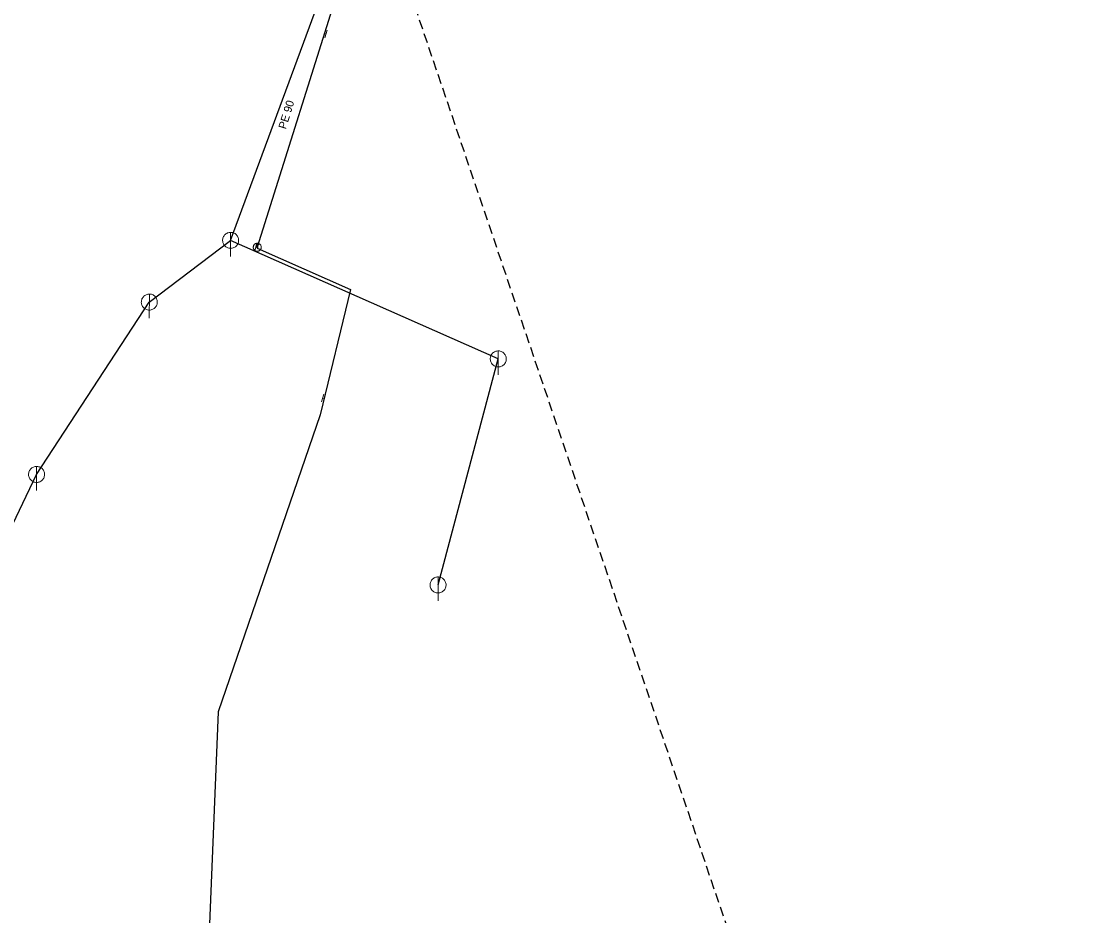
# Model space of a CAD drawing. Extents: x -659250 to -657316, y -997555 to -993684.
# Drawn here: x -658490.2 to -658358.7, y -994287.5 to -994175.8 of the extents above; entities that cross this region are included whole.
import ezdxf

# ---------------------------------------------------------------- set-up
doc = ezdxf.new("R2010")
doc.units = 0
doc.header["$LTSCALE"] = 0.4
doc.linetypes.add('MEDIUM_DASHED', pattern=[4.5, 3, -1.5])
doc.layers.add('1', color=7, linetype='Continuous')
for name, color, linetype, lineweight in [('14', 7, 'Continuous', 25), ('17', 7, 'Continuous', 25), ('22', 7, 'Continuous', 13), ('34', 7, 'Continuous', 13), ('47', 7, 'Continuous', 13), ('63', 7, 'MEDIUM_DASHED', 25), ('9', 7, 'Continuous', 13)]:
    doc.layers.add(name, color=color, linetype=linetype, lineweight=lineweight)

msp = doc.modelspace()

# ---------------------------------------------------------------- linework, layer by layer
at = {"layer": '14', "lineweight": 13}
for p, q in [((-658452.347, -994177.312), (-658452.14, -994177.379)), ((-658452.359, -994222.893), (-658452.55, -994222.84))]:
    msp.add_line(p, q, dxfattribs=at)
at = {"layer": '14'}
for p, q in [((-658430.62, -994217.949), (-658464.05, -994203.14)), ((-658488.28, -994232.379), (-658474.199, -994210.85)), ((-658438.14, -994246.18), (-658430.62, -994217.949))]:
    msp.add_line(p, q, dxfattribs=at)
for points in [[(-658474.199, -994210.85), (-658464.05, -994203.14), (-658452.78, -994172.6)], [(-658503.5, -994286.66), (-658500.649, -994258.26), (-658488.28, -994232.379)]]:
    msp.add_lwpolyline(points, dxfattribs=at)
at = {"layer": '14', "lineweight": 13}
msp.add_lwpolyline([(-658460.72, -994204.005), (-658460.899, -994203.96), (-658460.68, -994203.62)], dxfattribs=at)
at = {"layer": '17'}
for points in [[(-658452.813, -994094.017), (-658447.552, -994118.497), (-658457.625, -994125.125), (-658454.477, -994135.613), (-658450.198, -994170.463), (-658460.72, -994204.005)], [(-658460.72, -994204.005), (-658460.75, -994204.1), (-658449.09, -994209.27), (-658452.845, -994224.92), (-658465.59, -994262.02), (-658467.846, -994317.061), (-658460.533, -994343.112)]]:
    msp.add_lwpolyline(points, dxfattribs=at)
at = {"layer": '22'}
for p, q in [((-658464.05, -994205.14), (-658464.049, -994202.14)), ((-658474.199, -994212.85), (-658474.198, -994209.85)), ((-658430.62, -994219.949), (-658430.619, -994216.949)), ((-658488.28, -994234.379), (-658488.279, -994231.379)), ((-658438.14, -994248.18), (-658438.139, -994245.18))]:
    msp.add_line(p, q, dxfattribs=at)
for points in [[(-658463.05, -994203.14), (-658463.055, -994203.031), (-658463.073, -994202.923), (-658463.103, -994202.817), (-658463.143, -994202.716), (-658463.195, -994202.619), (-658463.257, -994202.529), (-658463.329, -994202.446), (-658463.409, -994202.372), (-658463.497, -994202.306), (-658463.591, -994202.251), (-658463.691, -994202.206), (-658463.796, -994202.173), (-658463.903, -994202.151), (-658464.012, -994202.141), (-658464.122, -994202.143), (-658464.23, -994202.157), (-658464.337, -994202.182), (-658464.44, -994202.219), (-658464.538, -994202.268), (-658464.63, -994202.326), (-658464.716, -994202.395), (-658464.793, -994202.472), (-658464.862, -994202.558), (-658464.921, -994202.65), (-658464.969, -994202.748), (-658465.006, -994202.851), (-658465.032, -994202.958), (-658465.046, -994203.066), (-658465.049, -994203.176), (-658465.039, -994203.285), (-658465.018, -994203.392), (-658464.984, -994203.496), (-658464.94, -994203.596), (-658464.885, -994203.691), (-658464.819, -994203.779), (-658464.745, -994203.859), (-658464.662, -994203.931), (-658464.572, -994203.993), (-658464.476, -994204.045), (-658464.374, -994204.086), (-658464.269, -994204.116), (-658464.161, -994204.134), (-658464.051, -994204.14), (-658463.942, -994204.134), (-658463.834, -994204.116), (-658463.729, -994204.087), (-658463.627, -994204.046), (-658463.53, -994203.994), (-658463.44, -994203.932), (-658463.357, -994203.861), (-658463.282, -994203.781), (-658463.217, -994203.693), (-658463.161, -994203.599), (-658463.117, -994203.499), (-658463.083, -994203.395), (-658463.061, -994203.287), (-658463.051, -994203.178)], [(-658473.199, -994210.85), (-658473.204, -994210.741), (-658473.222, -994210.633), (-658473.252, -994210.527), (-658473.292, -994210.426), (-658473.344, -994210.329), (-658473.406, -994210.239), (-658473.478, -994210.156), (-658473.558, -994210.082), (-658473.646, -994210.016), (-658473.74, -994209.961), (-658473.84, -994209.916), (-658473.945, -994209.883), (-658474.052, -994209.861), (-658474.161, -994209.851), (-658474.271, -994209.853), (-658474.379, -994209.867), (-658474.486, -994209.892), (-658474.589, -994209.929), (-658474.687, -994209.978), (-658474.779, -994210.036), (-658474.865, -994210.105), (-658474.942, -994210.182), (-658475.011, -994210.268), (-658475.07, -994210.36), (-658475.118, -994210.458), (-658475.155, -994210.561), (-658475.181, -994210.668), (-658475.195, -994210.776), (-658475.198, -994210.886), (-658475.188, -994210.995), (-658475.167, -994211.102), (-658475.133, -994211.206), (-658475.089, -994211.306), (-658475.034, -994211.401), (-658474.968, -994211.489), (-658474.894, -994211.569), (-658474.811, -994211.641), (-658474.721, -994211.703), (-658474.625, -994211.755), (-658474.523, -994211.796), (-658474.418, -994211.826), (-658474.31, -994211.844), (-658474.2, -994211.85), (-658474.091, -994211.844), (-658473.983, -994211.826), (-658473.878, -994211.797), (-658473.776, -994211.756), (-658473.679, -994211.704), (-658473.589, -994211.642), (-658473.506, -994211.571), (-658473.431, -994211.491), (-658473.366, -994211.403), (-658473.31, -994211.309), (-658473.266, -994211.209), (-658473.232, -994211.105), (-658473.21, -994210.997), (-658473.2, -994210.888)], [(-658429.62, -994217.949), (-658429.625, -994217.84), (-658429.643, -994217.732), (-658429.673, -994217.626), (-658429.713, -994217.525), (-658429.765, -994217.428), (-658429.827, -994217.338), (-658429.899, -994217.255), (-658429.979, -994217.181), (-658430.067, -994217.115), (-658430.161, -994217.06), (-658430.261, -994217.015), (-658430.366, -994216.982), (-658430.473, -994216.96), (-658430.582, -994216.95), (-658430.692, -994216.952), (-658430.8, -994216.966), (-658430.907, -994216.991), (-658431.01, -994217.028), (-658431.108, -994217.077), (-658431.2, -994217.135), (-658431.286, -994217.204), (-658431.363, -994217.281), (-658431.432, -994217.367), (-658431.491, -994217.459), (-658431.539, -994217.557), (-658431.576, -994217.66), (-658431.602, -994217.767), (-658431.616, -994217.875), (-658431.619, -994217.985), (-658431.609, -994218.094), (-658431.588, -994218.201), (-658431.554, -994218.305), (-658431.51, -994218.405), (-658431.455, -994218.5), (-658431.389, -994218.588), (-658431.315, -994218.668), (-658431.232, -994218.74), (-658431.142, -994218.802), (-658431.046, -994218.854), (-658430.944, -994218.895), (-658430.839, -994218.925), (-658430.731, -994218.943), (-658430.621, -994218.949), (-658430.512, -994218.943), (-658430.404, -994218.925), (-658430.299, -994218.896), (-658430.197, -994218.855), (-658430.1, -994218.803), (-658430.01, -994218.741), (-658429.927, -994218.67), (-658429.852, -994218.59), (-658429.787, -994218.502), (-658429.731, -994218.408), (-658429.687, -994218.308), (-658429.653, -994218.204), (-658429.631, -994218.096), (-658429.621, -994217.987)], [(-658487.28, -994232.379), (-658487.285, -994232.27), (-658487.303, -994232.162), (-658487.333, -994232.056), (-658487.373, -994231.955), (-658487.425, -994231.858), (-658487.487, -994231.768), (-658487.559, -994231.685), (-658487.639, -994231.611), (-658487.727, -994231.545), (-658487.821, -994231.49), (-658487.921, -994231.445), (-658488.026, -994231.412), (-658488.133, -994231.39), (-658488.242, -994231.38), (-658488.352, -994231.382), (-658488.46, -994231.396), (-658488.567, -994231.421), (-658488.67, -994231.458), (-658488.768, -994231.507), (-658488.86, -994231.565), (-658488.946, -994231.634), (-658489.023, -994231.711), (-658489.092, -994231.797), (-658489.151, -994231.889), (-658489.199, -994231.987), (-658489.236, -994232.09), (-658489.262, -994232.197), (-658489.276, -994232.305), (-658489.279, -994232.415), (-658489.269, -994232.524), (-658489.248, -994232.631), (-658489.214, -994232.735), (-658489.17, -994232.835), (-658489.115, -994232.93), (-658489.049, -994233.018), (-658488.975, -994233.098), (-658488.892, -994233.17), (-658488.802, -994233.232), (-658488.706, -994233.284), (-658488.604, -994233.325), (-658488.499, -994233.355), (-658488.391, -994233.373), (-658488.281, -994233.379), (-658488.172, -994233.373), (-658488.064, -994233.355), (-658487.959, -994233.326), (-658487.857, -994233.285), (-658487.76, -994233.233), (-658487.67, -994233.171), (-658487.587, -994233.1), (-658487.512, -994233.02), (-658487.447, -994232.932), (-658487.391, -994232.838), (-658487.347, -994232.738), (-658487.313, -994232.634), (-658487.291, -994232.526), (-658487.281, -994232.417)], [(-658437.14, -994246.18), (-658437.145, -994246.071), (-658437.163, -994245.963), (-658437.193, -994245.857), (-658437.233, -994245.756), (-658437.285, -994245.659), (-658437.347, -994245.569), (-658437.419, -994245.486), (-658437.499, -994245.412), (-658437.587, -994245.346), (-658437.681, -994245.291), (-658437.781, -994245.246), (-658437.886, -994245.213), (-658437.993, -994245.191), (-658438.102, -994245.181), (-658438.212, -994245.183), (-658438.32, -994245.197), (-658438.427, -994245.222), (-658438.53, -994245.259), (-658438.628, -994245.308), (-658438.72, -994245.366), (-658438.806, -994245.435), (-658438.883, -994245.512), (-658438.952, -994245.598), (-658439.011, -994245.69), (-658439.059, -994245.788), (-658439.096, -994245.891), (-658439.122, -994245.998), (-658439.136, -994246.106), (-658439.139, -994246.216), (-658439.129, -994246.325), (-658439.108, -994246.432), (-658439.074, -994246.536), (-658439.03, -994246.636), (-658438.975, -994246.731), (-658438.909, -994246.819), (-658438.835, -994246.899), (-658438.752, -994246.971), (-658438.662, -994247.033), (-658438.566, -994247.085), (-658438.464, -994247.126), (-658438.359, -994247.156), (-658438.251, -994247.174), (-658438.141, -994247.18), (-658438.032, -994247.174), (-658437.924, -994247.156), (-658437.819, -994247.127), (-658437.717, -994247.086), (-658437.62, -994247.034), (-658437.53, -994246.972), (-658437.447, -994246.901), (-658437.372, -994246.821), (-658437.307, -994246.733), (-658437.251, -994246.639), (-658437.207, -994246.539), (-658437.173, -994246.435), (-658437.151, -994246.327), (-658437.141, -994246.218)]]:
    msp.add_lwpolyline(points, close=True, dxfattribs=at)
at = {"layer": '34'}
for p, q in [((-658451.986, -994176.903), (-658452.294, -994177.854)), ((-658461.021, -994204.444), (-658460.775, -994203.475)), ((-658452.683, -994223.321), (-658452.415, -994222.358))]:
    msp.add_line(p, q, dxfattribs=at)
at = {"layer": '47'}
for points in [[(-658460.22, -994204.005), (-658460.223, -994203.953), (-658460.231, -994203.901), (-658460.245, -994203.851), (-658460.262, -994203.802), (-658460.287, -994203.755), (-658460.316, -994203.711), (-658460.348, -994203.671), (-658460.386, -994203.634), (-658460.426, -994203.601), (-658460.47, -994203.572), (-658460.517, -994203.548), (-658460.566, -994203.53), (-658460.615, -994203.516), (-658460.668, -994203.508), (-658460.72, -994203.505), (-658460.772, -994203.508), (-658460.824, -994203.516), (-658460.875, -994203.53), (-658460.923, -994203.548), (-658460.97, -994203.572), (-658461.014, -994203.601), (-658461.054, -994203.634), (-658461.092, -994203.671), (-658461.125, -994203.711), (-658461.152, -994203.755), (-658461.177, -994203.802), (-658461.196, -994203.851), (-658461.208, -994203.901), (-658461.217, -994203.953), (-658461.22, -994204.005), (-658461.217, -994204.057), (-658461.208, -994204.109), (-658461.196, -994204.16), (-658461.177, -994204.208), (-658461.152, -994204.255), (-658461.125, -994204.299), (-658461.092, -994204.34), (-658461.054, -994204.377), (-658461.014, -994204.41), (-658460.97, -994204.438), (-658460.923, -994204.462), (-658460.875, -994204.481), (-658460.824, -994204.494), (-658460.772, -994204.502), (-658460.72, -994204.505), (-658460.668, -994204.502), (-658460.615, -994204.494), (-658460.566, -994204.481), (-658460.517, -994204.462), (-658460.47, -994204.438), (-658460.426, -994204.41), (-658460.386, -994204.377), (-658460.348, -994204.34), (-658460.316, -994204.299), (-658460.287, -994204.255), (-658460.262, -994204.208), (-658460.245, -994204.16), (-658460.231, -994204.109), (-658460.223, -994204.057)], [(-658460.637, -994204.005), (-658460.637, -994203.996), (-658460.64, -994203.988), (-658460.642, -994203.98), (-658460.645, -994203.972), (-658460.649, -994203.964), (-658460.654, -994203.957), (-658460.659, -994203.95), (-658460.664, -994203.944), (-658460.672, -994203.939), (-658460.679, -994203.934), (-658460.686, -994203.93), (-658460.695, -994203.927), (-658460.703, -994203.925), (-658460.711, -994203.923), (-658460.72, -994203.923), (-658460.728, -994203.923), (-658460.737, -994203.925), (-658460.745, -994203.927), (-658460.753, -994203.93), (-658460.761, -994203.934), (-658460.767, -994203.939), (-658460.775, -994203.944), (-658460.781, -994203.95), (-658460.787, -994203.957), (-658460.791, -994203.964), (-658460.794, -994203.972), (-658460.798, -994203.98), (-658460.799, -994203.988), (-658460.802, -994203.996), (-658460.802, -994204.005), (-658460.802, -994204.014), (-658460.799, -994204.022), (-658460.798, -994204.03), (-658460.794, -994204.038), (-658460.791, -994204.046), (-658460.787, -994204.053), (-658460.781, -994204.06), (-658460.775, -994204.066), (-658460.767, -994204.072), (-658460.761, -994204.076), (-658460.753, -994204.08), (-658460.745, -994204.083), (-658460.737, -994204.085), (-658460.728, -994204.087), (-658460.72, -994204.087), (-658460.711, -994204.087), (-658460.703, -994204.085), (-658460.695, -994204.083), (-658460.686, -994204.08), (-658460.679, -994204.076), (-658460.672, -994204.072), (-658460.664, -994204.066), (-658460.659, -994204.06), (-658460.654, -994204.053), (-658460.649, -994204.046), (-658460.645, -994204.038), (-658460.642, -994204.03), (-658460.64, -994204.022), (-658460.637, -994204.014)]]:
    msp.add_lwpolyline(points, close=True, dxfattribs=at)
at = {"layer": '63'}
msp.add_lwpolyline([(-659116.685, -993855.266), (-658551.464, -993848.288), (-658551.464, -993848.288), (-657316.352, -997490.822), (-657316.352, -997490.822), (-657839.705, -997490.822), (-657839.705, -997490.822)], close=True, dxfattribs=at)
at = {"layer": '9'}
for points in [[(-658460.806, -994203.62), (-658460.806, -994203.633), (-658460.804, -994203.646), (-658460.801, -994203.659), (-658460.796, -994203.671), (-658460.79, -994203.683), (-658460.783, -994203.694), (-658460.775, -994203.704), (-658460.765, -994203.714), (-658460.755, -994203.722), (-658460.744, -994203.729), (-658460.732, -994203.735), (-658460.72, -994203.74), (-658460.707, -994203.743), (-658460.694, -994203.745), (-658460.681, -994203.747), (-658460.668, -994203.746), (-658460.655, -994203.744), (-658460.642, -994203.741), (-658460.63, -994203.736), (-658460.618, -994203.73), (-658460.607, -994203.723), (-658460.597, -994203.715), (-658460.587, -994203.705), (-658460.579, -994203.695), (-658460.572, -994203.684), (-658460.566, -994203.672), (-658460.561, -994203.66), (-658460.558, -994203.647), (-658460.556, -994203.634), (-658460.554, -994203.621), (-658460.555, -994203.608), (-658460.557, -994203.595), (-658460.56, -994203.582), (-658460.565, -994203.57), (-658460.571, -994203.558), (-658460.578, -994203.547), (-658460.586, -994203.537), (-658460.596, -994203.527), (-658460.606, -994203.519), (-658460.617, -994203.512), (-658460.629, -994203.506), (-658460.641, -994203.501), (-658460.654, -994203.498), (-658460.667, -994203.496), (-658460.68, -994203.495), (-658460.693, -994203.495), (-658460.706, -994203.497), (-658460.719, -994203.5), (-658460.731, -994203.505), (-658460.743, -994203.511), (-658460.754, -994203.518), (-658460.764, -994203.526), (-658460.774, -994203.536), (-658460.782, -994203.546), (-658460.789, -994203.557), (-658460.795, -994203.569), (-658460.8, -994203.581), (-658460.803, -994203.594), (-658460.805, -994203.607)], [(-658460.786, -994203.62), (-658460.787, -994203.631), (-658460.785, -994203.642), (-658460.782, -994203.653), (-658460.778, -994203.663), (-658460.773, -994203.673), (-658460.767, -994203.682), (-658460.76, -994203.691), (-658460.752, -994203.699), (-658460.743, -994203.706), (-658460.734, -994203.712), (-658460.724, -994203.717), (-658460.714, -994203.721), (-658460.703, -994203.724), (-658460.692, -994203.727), (-658460.681, -994203.727), (-658460.67, -994203.727), (-658460.659, -994203.725), (-658460.648, -994203.722), (-658460.638, -994203.718), (-658460.628, -994203.713), (-658460.619, -994203.707), (-658460.61, -994203.7), (-658460.602, -994203.692), (-658460.595, -994203.683), (-658460.589, -994203.674), (-658460.584, -994203.664), (-658460.58, -994203.654), (-658460.577, -994203.643), (-658460.575, -994203.632), (-658460.574, -994203.621), (-658460.574, -994203.61), (-658460.576, -994203.599), (-658460.579, -994203.588), (-658460.583, -994203.578), (-658460.588, -994203.568), (-658460.594, -994203.559), (-658460.601, -994203.55), (-658460.609, -994203.542), (-658460.618, -994203.535), (-658460.627, -994203.529), (-658460.637, -994203.524), (-658460.647, -994203.52), (-658460.658, -994203.517), (-658460.669, -994203.515), (-658460.68, -994203.515), (-658460.691, -994203.514), (-658460.702, -994203.516), (-658460.713, -994203.519), (-658460.723, -994203.523), (-658460.733, -994203.528), (-658460.742, -994203.534), (-658460.751, -994203.541), (-658460.759, -994203.549), (-658460.766, -994203.558), (-658460.772, -994203.567), (-658460.777, -994203.577), (-658460.781, -994203.587), (-658460.784, -994203.598), (-658460.786, -994203.609)], [(-658460.767, -994203.62), (-658460.767, -994203.629), (-658460.766, -994203.638), (-658460.763, -994203.647), (-658460.76, -994203.655), (-658460.756, -994203.663), (-658460.751, -994203.671), (-658460.745, -994203.678), (-658460.739, -994203.684), (-658460.732, -994203.69), (-658460.724, -994203.695), (-658460.716, -994203.699), (-658460.708, -994203.702), (-658460.699, -994203.705), (-658460.69, -994203.706), (-658460.681, -994203.708), (-658460.672, -994203.707), (-658460.663, -994203.706), (-658460.654, -994203.703), (-658460.646, -994203.7), (-658460.638, -994203.696), (-658460.63, -994203.691), (-658460.623, -994203.685), (-658460.617, -994203.679), (-658460.611, -994203.672), (-658460.606, -994203.664), (-658460.602, -994203.656), (-658460.599, -994203.648), (-658460.596, -994203.639), (-658460.595, -994203.63), (-658460.593, -994203.621), (-658460.594, -994203.612), (-658460.595, -994203.603), (-658460.598, -994203.594), (-658460.601, -994203.586), (-658460.605, -994203.578), (-658460.61, -994203.57), (-658460.616, -994203.563), (-658460.622, -994203.557), (-658460.629, -994203.551), (-658460.637, -994203.546), (-658460.645, -994203.542), (-658460.653, -994203.539), (-658460.662, -994203.536), (-658460.671, -994203.535), (-658460.68, -994203.534), (-658460.689, -994203.534), (-658460.698, -994203.535), (-658460.707, -994203.538), (-658460.715, -994203.541), (-658460.723, -994203.545), (-658460.731, -994203.55), (-658460.738, -994203.556), (-658460.744, -994203.562), (-658460.75, -994203.569), (-658460.755, -994203.577), (-658460.759, -994203.585), (-658460.762, -994203.593), (-658460.765, -994203.602), (-658460.766, -994203.611)], [(-658460.747, -994203.62), (-658460.747, -994203.627), (-658460.746, -994203.634), (-658460.745, -994203.641), (-658460.742, -994203.647), (-658460.739, -994203.653), (-658460.735, -994203.659), (-658460.731, -994203.665), (-658460.726, -994203.67), (-658460.72, -994203.674), (-658460.714, -994203.678), (-658460.708, -994203.681), (-658460.702, -994203.684), (-658460.695, -994203.685), (-658460.688, -994203.688), (-658460.681, -994203.688), (-658460.674, -994203.688), (-658460.667, -994203.686), (-658460.66, -994203.685), (-658460.654, -994203.682), (-658460.647, -994203.679), (-658460.642, -994203.675), (-658460.636, -994203.671), (-658460.631, -994203.666), (-658460.627, -994203.66), (-658460.623, -994203.654), (-658460.62, -994203.648), (-658460.617, -994203.642), (-658460.615, -994203.635), (-658460.614, -994203.628), (-658460.613, -994203.621), (-658460.613, -994203.614), (-658460.614, -994203.607), (-658460.616, -994203.6), (-658460.619, -994203.594), (-658460.622, -994203.587), (-658460.626, -994203.582), (-658460.63, -994203.576), (-658460.635, -994203.571), (-658460.641, -994203.567), (-658460.646, -994203.563), (-658460.653, -994203.56), (-658460.659, -994203.557), (-658460.666, -994203.555), (-658460.673, -994203.554), (-658460.68, -994203.554), (-658460.687, -994203.554), (-658460.694, -994203.554), (-658460.701, -994203.556), (-658460.707, -994203.559), (-658460.713, -994203.562), (-658460.719, -994203.566), (-658460.725, -994203.57), (-658460.73, -994203.575), (-658460.734, -994203.581), (-658460.738, -994203.586), (-658460.741, -994203.593), (-658460.744, -994203.599), (-658460.745, -994203.606), (-658460.747, -994203.613)], [(-658460.727, -994203.62), (-658460.727, -994203.625), (-658460.727, -994203.63), (-658460.726, -994203.635), (-658460.724, -994203.639), (-658460.722, -994203.644), (-658460.719, -994203.648), (-658460.716, -994203.651), (-658460.712, -994203.655), (-658460.709, -994203.658), (-658460.705, -994203.661), (-658460.7, -994203.663), (-658460.696, -994203.665), (-658460.691, -994203.666), (-658460.686, -994203.668), (-658460.681, -994203.668), (-658460.676, -994203.668), (-658460.671, -994203.667), (-658460.666, -994203.666), (-658460.662, -994203.664), (-658460.657, -994203.662), (-658460.653, -994203.659), (-658460.649, -994203.656), (-658460.646, -994203.652), (-658460.643, -994203.649), (-658460.64, -994203.645), (-658460.638, -994203.64), (-658460.636, -994203.636), (-658460.635, -994203.631), (-658460.634, -994203.626), (-658460.633, -994203.621), (-658460.633, -994203.616), (-658460.634, -994203.611), (-658460.635, -994203.606), (-658460.637, -994203.602), (-658460.639, -994203.597), (-658460.642, -994203.593), (-658460.645, -994203.589), (-658460.648, -994203.586), (-658460.652, -994203.583), (-658460.656, -994203.58), (-658460.661, -994203.578), (-658460.665, -994203.576), (-658460.67, -994203.575), (-658460.675, -994203.574), (-658460.68, -994203.574), (-658460.685, -994203.574), (-658460.69, -994203.575), (-658460.695, -994203.575), (-658460.699, -994203.577), (-658460.704, -994203.579), (-658460.708, -994203.582), (-658460.711, -994203.585), (-658460.715, -994203.588), (-658460.718, -994203.592), (-658460.721, -994203.596), (-658460.723, -994203.601), (-658460.725, -994203.605), (-658460.726, -994203.61), (-658460.727, -994203.615)], [(-658460.707, -994203.62), (-658460.707, -994203.623), (-658460.708, -994203.626), (-658460.707, -994203.628), (-658460.706, -994203.631), (-658460.705, -994203.634), (-658460.703, -994203.636), (-658460.701, -994203.638), (-658460.699, -994203.64), (-658460.697, -994203.642), (-658460.695, -994203.644), (-658460.692, -994203.646), (-658460.689, -994203.647), (-658460.687, -994203.647), (-658460.684, -994203.648), (-658460.681, -994203.648), (-658460.678, -994203.648), (-658460.675, -994203.648), (-658460.672, -994203.647), (-658460.67, -994203.646), (-658460.667, -994203.645), (-658460.665, -994203.643), (-658460.662, -994203.641), (-658460.66, -994203.639), (-658460.659, -994203.637), (-658460.657, -994203.635), (-658460.656, -994203.632), (-658460.654, -994203.629), (-658460.654, -994203.627), (-658460.653, -994203.624), (-658460.652, -994203.621), (-658460.653, -994203.618), (-658460.653, -994203.615), (-658460.654, -994203.612), (-658460.655, -994203.61), (-658460.656, -994203.607), (-658460.658, -994203.605), (-658460.659, -994203.602), (-658460.661, -994203.6), (-658460.664, -994203.599), (-658460.666, -994203.597), (-658460.669, -994203.596), (-658460.671, -994203.595), (-658460.674, -994203.594), (-658460.677, -994203.594), (-658460.68, -994203.593), (-658460.683, -994203.594), (-658460.686, -994203.593), (-658460.688, -994203.595), (-658460.691, -994203.595), (-658460.694, -994203.596), (-658460.696, -994203.598), (-658460.698, -994203.599), (-658460.7, -994203.601), (-658460.702, -994203.604), (-658460.704, -994203.606), (-658460.705, -994203.609), (-658460.706, -994203.611), (-658460.707, -994203.614), (-658460.707, -994203.617)], [(-658460.688, -994203.62), (-658460.688, -994203.622), (-658460.688, -994203.622), (-658460.687, -994203.622), (-658460.687, -994203.624), (-658460.688, -994203.625), (-658460.686, -994203.625), (-658460.686, -994203.625), (-658460.686, -994203.627), (-658460.686, -994203.627), (-658460.685, -994203.628), (-658460.683, -994203.628), (-658460.683, -994203.628), (-658460.683, -994203.629), (-658460.681, -994203.629), (-658460.681, -994203.629), (-658460.68, -994203.629), (-658460.679, -994203.629), (-658460.679, -994203.628), (-658460.678, -994203.628), (-658460.676, -994203.628), (-658460.676, -994203.627), (-658460.676, -994203.627), (-658460.675, -994203.626), (-658460.675, -994203.626), (-658460.673, -994203.625), (-658460.673, -994203.624), (-658460.672, -994203.623), (-658460.672, -994203.623), (-658460.672, -994203.622), (-658460.672, -994203.621), (-658460.672, -994203.62), (-658460.672, -994203.619), (-658460.672, -994203.619), (-658460.673, -994203.618), (-658460.673, -994203.617), (-658460.674, -994203.616), (-658460.674, -994203.616), (-658460.675, -994203.615), (-658460.675, -994203.615), (-658460.676, -994203.614), (-658460.677, -994203.614), (-658460.678, -994203.613), (-658460.678, -994203.613), (-658460.679, -994203.613), (-658460.68, -994203.613), (-658460.681, -994203.613), (-658460.682, -994203.613), (-658460.682, -994203.613), (-658460.683, -994203.614), (-658460.684, -994203.613), (-658460.685, -994203.615), (-658460.685, -994203.615), (-658460.686, -994203.615), (-658460.686, -994203.615), (-658460.687, -994203.617), (-658460.687, -994203.618), (-658460.687, -994203.619), (-658460.688, -994203.619), (-658460.688, -994203.62)]]:
    msp.add_lwpolyline(points, close=True, dxfattribs=at)

# ---------------------------------------------------------------- texts
at = {"layer": '1'}
msp.add_text('PE 90 ', height=1, rotation=73, dxfattribs=at).set_placement((-658457.147, -994189.324))

doc.saveas('drawing.dxf')
